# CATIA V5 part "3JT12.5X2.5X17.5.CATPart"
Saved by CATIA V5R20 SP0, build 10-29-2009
Part number: 3JT12.5X2.5X17.5
Revision: ANY
Definition: UNKNOWN
Nomenclature: 3JT12.5X2.5X17.5
Source: Unknown
Bounding box of the stored display mesh (mm): x -8.75 to 8.75, y -1.25 to 1.25, z -8.75 to 8.75
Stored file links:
  C:\Users\Utente\Desktop\IO LAVORO\3D X SITO CF\CUMSA\3D files PW\pw101430\pw101430_ejection\3JT12.5X2.5X17.5.CATPart
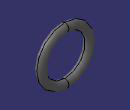
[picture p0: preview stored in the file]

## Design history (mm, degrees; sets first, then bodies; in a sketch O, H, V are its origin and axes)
Body1 "Revolución1" (main body)
  Solid1: solid without history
